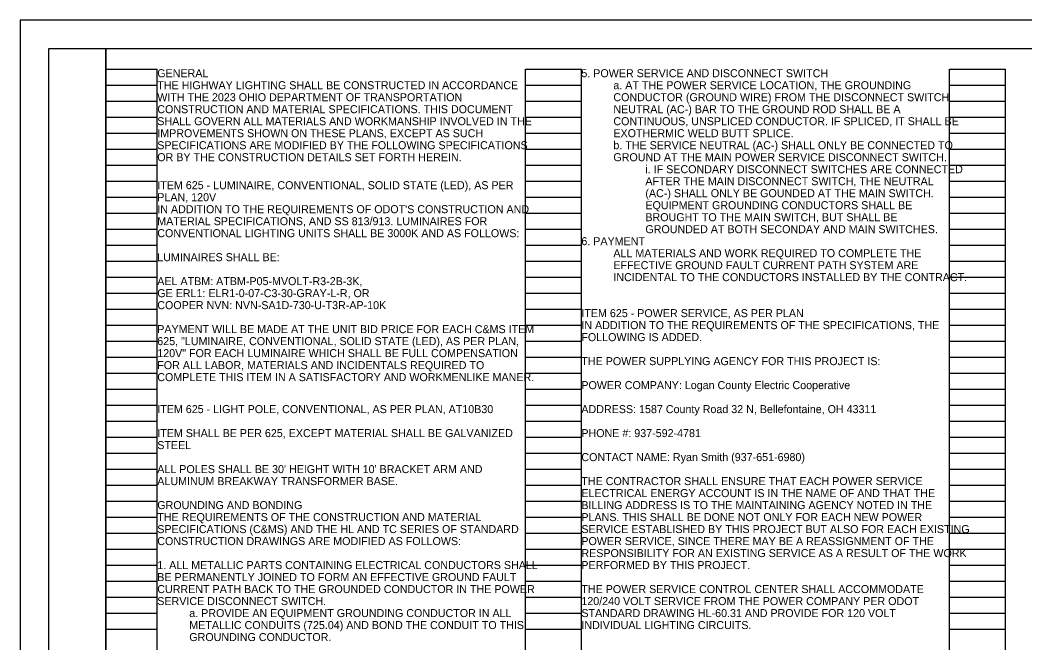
# Model space of a CAD drawing. Extents: x 0 to 34, y 0 to 22.
# Drawn here: x 0 to 17.58, y 11.1 to 22 of the extents above; entities that cross this region are included whole.
import ezdxf

# ---------------------------------------------------------------- set-up
doc = ezdxf.new("R2010")
doc.units = 0
for name, color, linetype in [('SH_Border', 7, 'Continuous'), ('SH_Cut_Line', 7, 'Continuous'), ('SH_Data', 7, 'Continuous'), ('SH_Text', 7, 'Continuous')]:
    doc.layers.add(name, color=color, linetype=linetype)

msp = doc.modelspace()

# ---------------------------------------------------------------- linework, layer by layer
at = {"layer": 'SH_Border'}
for points in [[(0.5, 21.5), (1.5, 21.5), (1.5, 0.5), (0.5, 0.5)], [(1.5, 21.5), (33.5, 21.5), (33.5, 0.5), (1.5, 0.5)]]:
    msp.add_lwpolyline(points, close=True, dxfattribs=at)
at = {"layer": 'SH_Cut_Line'}
msp.add_lwpolyline([(0, 0), (34, 0), (34, 22), (0, 22)], close=True, dxfattribs=at)
at = {"layer": 'SH_Data'}
for p, q in [((1.5, 0.98), (1.5, 21.14)), ((1.5, 21.14), (2.4, 21.14)), ((2.4, 0.98), (2.4, 21.14)), ((8.84, 0.98), (8.84, 21.14)), ((8.84, 21.14), (9.82, 21.14)), ((9.82, 0.98), (9.82, 21.14)), ((16.26, 0.98), (16.26, 21.14)), ((16.26, 21.14), (17.24, 21.14)), ((17.24, 0.98), (17.24, 21.14)), ((1.5, 20.86), (2.4, 20.86)), ((8.84, 20.86), (9.82, 20.86)), ((16.26, 20.86), (17.24, 20.86)), ((1.5, 20.58), (2.4, 20.58)), ((8.84, 20.58), (9.82, 20.58)), ((16.26, 20.58), (17.24, 20.58)), ((1.5, 20.3), (2.4, 20.3)), ((8.84, 20.3), (9.82, 20.3)), ((16.26, 20.3), (17.24, 20.3)), ((1.5, 20.02), (2.4, 20.02)), ((8.84, 20.02), (9.82, 20.02)), ((16.26, 20.02), (17.24, 20.02)), ((1.5, 19.74), (2.4, 19.74)), ((8.84, 19.74), (9.82, 19.74)), ((16.26, 19.74), (17.24, 19.74)), ((1.5, 19.46), (2.4, 19.46)), ((8.84, 19.46), (9.82, 19.46)), ((16.26, 19.46), (17.24, 19.46)), ((1.5, 19.18), (2.4, 19.18)), ((8.84, 19.18), (9.82, 19.18)), ((16.26, 19.18), (17.24, 19.18)), ((1.5, 18.9), (2.4, 18.9)), ((8.84, 18.9), (9.82, 18.9)), ((16.26, 18.9), (17.24, 18.9)), ((1.5, 18.62), (2.4, 18.62)), ((8.84, 18.62), (9.82, 18.62)), ((16.26, 18.62), (17.24, 18.62)), ((1.5, 18.34), (2.4, 18.34)), ((8.84, 18.34), (9.82, 18.34)), ((16.26, 18.34), (17.24, 18.34)), ((1.5, 18.06), (2.4, 18.06)), ((8.84, 18.06), (9.82, 18.06)), ((16.26, 18.06), (17.24, 18.06)), ((1.5, 17.78), (2.4, 17.78)), ((8.84, 17.78), (9.82, 17.78)), ((16.26, 17.78), (17.24, 17.78)), ((1.5, 17.5), (2.4, 17.5)), ((8.84, 17.5), (9.82, 17.5)), ((16.26, 17.5), (17.24, 17.5)), ((1.5, 17.22), (2.4, 17.22)), ((8.84, 17.22), (9.82, 17.22)), ((16.26, 17.22), (17.24, 17.22)), ((1.5, 16.94), (2.4, 16.94)), ((8.84, 16.94), (9.82, 16.94)), ((16.26, 16.94), (17.24, 16.94)), ((1.5, 16.66), (2.4, 16.66)), ((8.84, 16.66), (9.82, 16.66)), ((16.26, 16.66), (17.24, 16.66)), ((1.5, 16.38), (2.4, 16.38)), ((8.84, 16.38), (9.82, 16.38)), ((16.26, 16.38), (17.24, 16.38)), ((1.5, 16.1), (2.4, 16.1)), ((8.84, 16.1), (9.82, 16.1)), ((16.26, 16.1), (17.24, 16.1)), ((1.5, 15.82), (2.4, 15.82)), ((8.84, 15.82), (9.82, 15.82)), ((16.26, 15.82), (17.24, 15.82)), ((1.5, 15.54), (2.4, 15.54)), ((8.84, 15.54), (9.82, 15.54)), ((16.26, 15.54), (17.24, 15.54)), ((1.5, 15.26), (2.4, 15.26)), ((8.84, 15.26), (9.82, 15.26)), ((16.26, 15.26), (17.24, 15.26)), ((1.5, 14.98), (2.4, 14.98)), ((8.84, 14.98), (9.82, 14.98)), ((16.26, 14.98), (17.24, 14.98)), ((1.5, 14.7), (2.4, 14.7)), ((8.84, 14.7), (9.82, 14.7)), ((16.26, 14.7), (17.24, 14.7)), ((1.5, 14.42), (2.4, 14.42)), ((8.84, 14.42), (9.82, 14.42)), ((16.26, 14.42), (17.24, 14.42)), ((1.5, 14.14), (2.4, 14.14)), ((8.84, 14.14), (9.82, 14.14)), ((16.26, 14.14), (17.24, 14.14)), ((1.5, 13.86), (2.4, 13.86)), ((8.84, 13.86), (9.82, 13.86)), ((16.26, 13.86), (17.24, 13.86)), ((1.5, 13.58), (2.4, 13.58)), ((8.84, 13.58), (9.82, 13.58)), ((16.26, 13.58), (17.24, 13.58)), ((1.5, 13.3), (2.4, 13.3)), ((8.84, 13.3), (9.82, 13.3)), ((16.26, 13.3), (17.24, 13.3)), ((1.5, 13.02), (2.4, 13.02)), ((8.84, 13.02), (9.82, 13.02)), ((16.26, 13.02), (17.24, 13.02)), ((1.5, 12.74), (2.4, 12.74)), ((8.84, 12.74), (9.82, 12.74)), ((16.26, 12.74), (17.24, 12.74)), ((1.5, 12.46), (2.4, 12.46)), ((8.84, 12.46), (9.82, 12.46)), ((16.26, 12.46), (17.24, 12.46)), ((1.5, 12.18), (2.4, 12.18)), ((8.84, 12.18), (9.82, 12.18)), ((16.26, 12.18), (17.24, 12.18)), ((1.5, 11.9), (2.4, 11.9)), ((8.84, 11.9), (9.82, 11.9)), ((16.26, 11.9), (17.24, 11.9)), ((1.5, 11.62), (2.4, 11.62)), ((8.84, 11.62), (9.82, 11.62)), ((16.26, 11.62), (17.24, 11.62)), ((1.5, 11.34), (2.4, 11.34)), ((8.84, 11.34), (9.82, 11.34)), ((16.26, 11.34), (17.24, 11.34))]:
    msp.add_line(p, q, dxfattribs=at)

# ---------------------------------------------------------------- texts
at = {"layer": 'SH_Text'}
for s, p in [('GENERAL', (2.4, 21)), ('5. POWER SERVICE AND DISCONNECT SWITCH ', (9.82, 21)), ('THE HIGHWAY LIGHTING SHALL BE CONSTRUCTED IN ACCORDANCE ', (2.4, 20.79)), ('a. AT THE POWER SERVICE LOCATION, THE GROUNDING ', (10.38, 20.79)), ('WITH THE 2023 OHIO DEPARTMENT OF TRANSPORTATION ', (2.4, 20.58)), ('CONDUCTOR (GROUND WIRE) FROM THE DISCONNECT SWITCH ', (10.38, 20.58)), ('CONSTRUCTION AND MATERIAL SPECIFICATIONS. THIS DOCUMENT ', (2.4, 20.37)), ('NEUTRAL (AC-) BAR TO THE GROUND ROD SHALL BE A ', (10.38, 20.37)), ('SHALL GOVERN ALL MATERIALS AND WORKMANSHIP INVOLVED IN THE ', (2.4, 20.16)), ('CONTINUOUS, UNSPLICED CONDUCTOR. IF SPLICED, IT SHALL BE ', (10.38, 20.16)), ('IMPROVEMENTS SHOWN ON THESE PLANS, EXCEPT AS SUCH ', (2.4, 19.95)), ('EXOTHERMIC WELD BUTT SPLICE.', (10.38, 19.95)), ('SPECIFICATIONS ARE MODIFIED BY THE FOLLOWING SPECIFICATIONS ', (2.4, 19.74)), ('b. THE SERVICE NEUTRAL (AC-) SHALL ONLY BE CONNECTED TO ', (10.38, 19.74)), ('OR BY THE CONSTRUCTION DETAILS SET FORTH HEREIN. ', (2.4, 19.53)), ('GROUND AT THE MAIN POWER SERVICE DISCONNECT SWITCH.', (10.38, 19.53)), ('i. IF SECONDARY DISCONNECT SWITCHES ARE CONNECTED ', (10.94, 19.32)), ('ITEM 625 - LUMINAIRE, CONVENTIONAL, SOLID STATE (LED), AS PER ', (2.4, 19.04)), ('AFTER THE MAIN DISCONNECT SWITCH, THE NEUTRAL ', (10.94, 19.11)), ('(AC-) SHALL ONLY BE GOUNDED AT THE MAIN SWITCH. ', (10.94, 18.9)), ('PLAN, 120V', (2.4, 18.83)), ('EQUIPMENT GROUNDING CONDUCTORS SHALL BE ', (10.94, 18.69)), ("IN ADDITION TO THE REQUIREMENTS OF ODOT'S CONSTRUCTION AND ", (2.4, 18.62)), ('MATERIAL SPECIFICATIONS, AND SS 813/913. LUMINAIRES FOR ', (2.4, 18.41)), ('BROUGHT TO THE MAIN SWITCH, BUT SHALL BE ', (10.94, 18.48)), ('CONVENTIONAL LIGHTING UNITS SHALL BE 3000K AND AS FOLLOWS:', (2.4, 18.2)), ('GROUNDED AT BOTH SECONDAY AND MAIN SWITCHES. ', (10.94, 18.27)), ('6. PAYMENT ', (9.82, 18.06)), ('ALL MATERIALS AND WORK REQUIRED TO COMPLETE THE ', (10.38, 17.85)), ('LUMINAIRES SHALL BE:', (2.4, 17.78)), ('EFFECTIVE GROUND FAULT CURRENT PATH SYSTEM ARE ', (10.38, 17.64)), ('AEL ATBM: ATBM-P05-MVOLT-R3-2B-3K,', (2.4, 17.36)), ('INCIDENTAL TO THE CONDUCTORS INSTALLED BY THE CONTRACT.', (10.38, 17.43)), ('GE ERL1: ELR1-0-07-C3-30-GRAY-L-R, OR', (2.4, 17.15)), ('COOPER NVN: NVN-SA1D-730-U-T3R-AP-10K', (2.4, 16.94)), ('ITEM 625 - POWER SERVICE, AS PER PLAN ', (9.82, 16.8)), ('IN ADDITION TO THE REQUIREMENTS OF THE SPECIFICATIONS, THE ', (9.82, 16.59)), ('PAYMENT WILL BE MADE AT THE UNIT BID PRICE FOR EACH C&MS ITEM ', (2.4, 16.52)), ('625, "LUMINAIRE, CONVENTIONAL, SOLID STATE (LED), AS PER PLAN, ', (2.4, 16.31)), ('FOLLOWING IS ADDED.', (9.82, 16.38)), ('120V" FOR EACH LUMINAIRE WHICH SHALL BE FULL COMPENSATION ', (2.4, 16.1)), ('FOR ALL LABOR, MATERIALS AND INCIDENTALS REQUIRED TO ', (2.4, 15.89)), ('THE POWER SUPPLYING AGENCY FOR THIS PROJECT IS:', (9.82, 15.96)), ('COMPLETE THIS ITEM IN A SATISFACTORY AND WORKMENLIKE MANER.', (2.4, 15.68)), ('POWER COMPANY: Logan County Electric Cooperative', (9.82, 15.54)), ('ITEM 625 - LIGHT POLE, CONVENTIONAL, AS PER PLAN, AT10B30', (2.4, 15.12)), ('ADDRESS: 1587 County Road 32 N, Bellefontaine, OH 43311', (9.82, 15.12)), ('ITEM SHALL BE PER 625, EXCEPT MATERIAL SHALL BE GALVANIZED ', (2.4, 14.7)), ('PHONE #: 937-592-4781', (9.82, 14.7)), ('STEEL', (2.4, 14.49)), ('CONTACT NAME: Ryan Smith (937-651-6980)', (9.82, 14.28)), ("ALL POLES SHALL BE 30' HEIGHT WITH 10' BRACKET ARM AND ", (2.4, 14.07)), ('ALUMINUM BREAKWAY TRANSFORMER BASE.', (2.4, 13.86)), ('THE CONTRACTOR SHALL ENSURE THAT EACH POWER SERVICE ', (9.82, 13.86)), ('ELECTRICAL ENERGY ACCOUNT IS IN THE NAME OF AND THAT THE ', (9.82, 13.65)), ('GROUNDING AND BONDING', (2.4, 13.44)), ('BILLING ADDRESS IS TO THE MAINTAINING AGENCY NOTED IN THE ', (9.82, 13.44)), ('THE REQUIREMENTS OF THE CONSTRUCTION AND MATERIAL ', (2.4, 13.23)), ('PLANS. THIS SHALL BE DONE NOT ONLY FOR EACH NEW POWER ', (9.82, 13.23)), ('SPECIFICATIONS (C&MS) AND THE HL AND TC SERIES OF STANDARD ', (2.4, 13.02)), ('SERVICE ESTABLISHED BY THIS PROJECT BUT ALSO FOR EACH EXISTING ', (9.82, 13.02)), ('CONSTRUCTION DRAWINGS ARE MODIFIED AS FOLLOWS:', (2.4, 12.81)), ('POWER SERVICE, SINCE THERE MAY BE A REASSIGNMENT OF THE ', (9.82, 12.81)), ('RESPONSIBILITY FOR AN EXISTING SERVICE AS A RESULT OF THE WORK ', (9.82, 12.6)), ('1. ALL METALLIC PARTS CONTAINING ELECTRICAL CONDUCTORS SHALL ', (2.4, 12.39)), ('PERFORMED BY THIS PROJECT.', (9.82, 12.39)), ('BE PERMANENTLY JOINED TO FORM AN EFFECTIVE GROUND FAULT ', (2.4, 12.18)), ('CURRENT PATH BACK TO THE GROUNDED CONDUCTOR IN THE POWER ', (2.4, 11.97)), ('THE POWER SERVICE CONTROL CENTER SHALL ACCOMMODATE ', (9.82, 11.97)), ('SERVICE DISCONNECT SWITCH.', (2.4, 11.76)), ('120/240 VOLT SERVICE FROM THE POWER COMPANY PER ODOT ', (9.82, 11.76)), ('a. PROVIDE AN EQUIPMENT GROUNDING CONDUCTOR IN ALL ', (2.96, 11.55)), ('STANDARD DRAWING HL-60.31 AND PROVIDE FOR 120 VOLT ', (9.82, 11.55)), ('METALLIC CONDUITS (725.04) AND BOND THE CONDUIT TO THIS ', (2.96, 11.34)), ('INDIVIDUAL LIGHTING CIRCUITS.', (9.82, 11.34)), ('GROUNDING CONDUCTOR.', (2.96, 11.13))]:
    msp.add_text(s, height=0.14, dxfattribs=at).set_placement(p)

doc.saveas('drawing.dxf')
